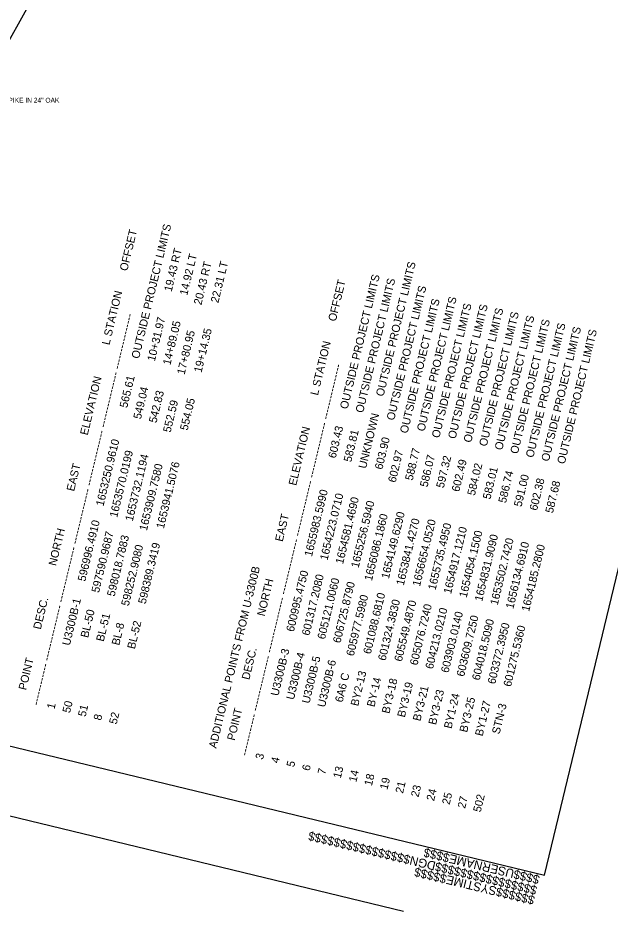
# Model space of a CAD drawing. Extents: x 1649669 to 1659218, y 588594 to 607900.
# Drawn here: x 1654574 to 1657042, y 595736 to 599457 of the extents above; entities that cross this region are included whole.
import ezdxf

# ---------------------------------------------------------------- set-up
doc = ezdxf.new("R2010")
doc.units = 0
for name, color, linetype in [('CTL Bench Mark Cogo Comment', 7, 'Continuous'), ('CTL Sheet Border CELL', 7, 'Continuous'), ('CTL Sheet Text', 7, 'Continuous'), ('Exist Roads EOP', 7, 'Continuous'), ('Sheet Cutting Line CELL', 7, 'Continuous')]:
    doc.layers.add(name, color=color, linetype=linetype)

msp = doc.modelspace()

# ---------------------------------------------------------------- linework, layer by layer
at = {"layer": 'CTL Sheet Border CELL'}
msp.add_line((1656768.8, 595886.6), (1656768.8, 595886.6), dxfattribs=at)
msp.add_line((1656768.8, 595886.6), (1656768.8, 595886.6), dxfattribs=at)
msp.add_line((1656768.8, 595886.6), (1656768.8, 595886.6), dxfattribs=at)
msp.add_line((1656768.8, 595886.6), (1656768.8, 595886.6), dxfattribs=at)
msp.add_line((1656768.8, 595886.6), (1656768.8, 595886.6), dxfattribs=at)
msp.add_line((1656768.8, 595886.6), (1656768.8, 595886.6), dxfattribs=at)
msp.add_line((1656768.8, 595886.6), (1656768.8, 595886.6), dxfattribs=at)
msp.add_line((1656768.8, 595886.6), (1656768.8, 595886.6), dxfattribs=at)
msp.add_line((1656768.8, 595886.6), (1656768.8, 595886.6), dxfattribs=at)
msp.add_line((1656768.8, 595886.6), (1656768.8, 595886.6), dxfattribs=at)
msp.add_line((1656768.8, 595886.6), (1656768.8, 595886.6), dxfattribs=at)
msp.add_lwpolyline([(1652117.6, 607744.3), (1649668.6, 597600.9), (1656768.8, 595886.6), (1659217.9, 606030)], close=True, dxfattribs=at)
msp.add_lwpolyline([(1656830.1, 596140.2), (1656830.1, 596140.2)], dxfattribs=at)
msp.add_lwpolyline([(1656830.1, 596140.2), (1656830.1, 596140.2)], dxfattribs=at)
at = {"layer": 'Exist Roads EOP'}
msp.add_line((1654170, 598706.6), (1654682.8, 599621.6), dxfattribs=at)
at = {"layer": 'Sheet Cutting Line CELL'}
msp.add_line((1649765.8, 597285.3), (1656181.4, 595736.3), dxfattribs=at)

# ---------------------------------------------------------------- texts
at = {"layer": 'CTL Bench Mark Cogo Comment'}
msp.add_text('RR SPIKE IN 24" OAK', height=20, dxfattribs=at).set_placement((1654468.7, 599103.7))
at = {"layer": 'CTL Sheet Border CELL'}
for s, p in [('$$$$$$$$$$$$$$$$DGN$$$$$$$$$$$$$$$$', (1656740.4, 595838.9)), ('$$$$USERNAME$$$$', (1656751, 595883.3)), ('$$$$$$SYSTIME$$$$$', (1656730.5, 595797.9))]:
    msp.add_text(s, height=36.522, rotation=166.4261, dxfattribs=at).set_placement(p)
at = {"layer": 'CTL Sheet Text'}
for s, height, p in [('    POINT          DESC.           NORTH             EAST          ELEVATION           L STATION       OFFSET', 33.3333, (1654596.9, 596606.4)), ('1                    U3300B-1      596996.4910     1653250.9610           565.61      OUTSIDE PROJECT LIMITS                 ', 33.3333, (1654726.5, 596575.1)), ('50                      BL-50      597590.9687     1653570.0199           549.04         10+31.97         19.43 RT', 33.3333, (1654791.3, 596559.4)), ('51                      BL-51      598018.7883     1653732.1194           542.83         14+89.05         14.92 LT', 33.3333, (1654856.1, 596543.8)), ('8                        BL-8      598252.9080     1653909.7580           552.59         17+80.95         20.43 RT', 33.3333, (1654920.9, 596528.1)), ('52                      BL-52      598389.3419     1653941.5076           554.05         19+14.35         22.31 LT', 33.3333, (1654985.7, 596512.5)), ('5                    U3300B-5      605121.0060     1654581.4690          UNKNOWN      OUTSIDE PROJECT LIMITS                 ', 33.3333, (1655725, 596334)), ('3                    U3300B-3      600995.4750     1655983.5990           603.43      OUTSIDE PROJECT LIMITS                 ', 33.3333, (1655595.4, 596365.3)), ('    POINT          DESC.           NORTH             EAST          ELEVATION           L STATION       OFFSET', 33.3333, (1655465.8, 596396.6)), ('4                    U3300B-4      601317.2080     1654223.0710           583.81      OUTSIDE PROJECT LIMITS                 ', 33.3333, (1655660.2, 596349.6)), ('6                    U3300B-6      606725.8790     1655256.5940           603.90      OUTSIDE PROJECT LIMITS                 ', 33.3333, (1655789.8, 596318.3)), ('7                       6A6 C      605977.5980     1656086.1860           602.97      OUTSIDE PROJECT LIMITS                 ', 33.3333, (1655854.6, 596302.7)), ('13                     BY2-13      601088.6810     1654149.6290           588.77      OUTSIDE PROJECT LIMITS                 ', 33.3333, (1655919.5, 596287)), ('14                      BY-14      601324.3830     1653841.4270           586.07      OUTSIDE PROJECT LIMITS                 ', 33.3333, (1655984.3, 596271.4)), ('18                     BY3-18      605549.4870     1656654.0520           597.32      OUTSIDE PROJECT LIMITS                 ', 33.3333, (1656049.1, 596255.7)), ('19                     BY3-19      605076.7240     1655735.4950           602.49      OUTSIDE PROJECT LIMITS                 ', 33.3333, (1656113.9, 596240.1)), ('21                     BY3-21      604213.0210     1654917.1210           584.02      OUTSIDE PROJECT LIMITS                 ', 33.3333, (1656178.7, 596224.4)), ('------------ ---------------- ---------------- ---------------- ---------------- ---------------- ----------------', 33.3333, (1654661.7, 596590.7)), ('23                     BY3-23      603903.0140     1654054.1500           583.01      OUTSIDE PROJECT LIMITS                 ', 33.3333, (1656243.5, 596208.8)), ('24                     BY1-24      603609.7250     1654831.9090           586.74      OUTSIDE PROJECT LIMITS                 ', 33.3333, (1656308.3, 596193.1)), ('25                     BY3-25      604018.5090     1653502.7420           591.00      OUTSIDE PROJECT LIMITS                 ', 33.3333, (1656373.1, 596177.5)), ('27                     BY1-27      603372.3950     1656134.6910           602.38      OUTSIDE PROJECT LIMITS                 ', 33.3333, (1656437.9, 596161.9)), ('502                     STN-3      601275.5360     1654185.2800           587.68      OUTSIDE PROJECT LIMITS                 ', 33.3333, (1656502.7, 596146.2)), ('------------ ---------------- ---------------- ---------------- ---------------- ---------------- ----------------', 33.3333, (1655530.6, 596380.9)), ('ADDITIONAL POINTS FROM U-3300B', 33.333, (1655401, 596412.2))]:
    msp.add_text(s, height=height, rotation=76.4261, dxfattribs=at).set_placement(p)

doc.saveas('drawing.dxf')
